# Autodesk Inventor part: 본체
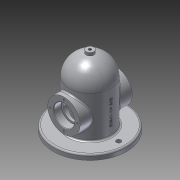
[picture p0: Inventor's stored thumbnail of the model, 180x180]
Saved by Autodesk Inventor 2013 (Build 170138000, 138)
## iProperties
Created: 2019-11
Part Number: 본체
Material: 알루미늄 6061
Document SubType Name: Modeling
Designer: Administrator
Density: 2.71 g/cm^3
Mass: 1110.07 g
Surface Area: 883.581 cm^2
Volume: 409.619 cm^3
Author: Administrator
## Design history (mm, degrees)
sketch "스케치4"
  geometry: C1 r 40 at (0, 0); 1 further point
  constraints: 1 centre point, 1 coincident
  dimensions: "d5" = 80 diameter of C1
extrude "돌출1" new body sketch "스케치4" distance "d7" = 90; taper "d8" = 0 deg
sketch "스케치5"
  geometry: L1 (-40, 0)-(-40, 90) reference; L2 (40, 90)-(-40, 90) reference; L3 (-40, 90)-(40, 90); L4 (40, 0)-(40, 90) reference; L5 (0, 0)-(0, 90); A1 r 40 centre (0, 90) between (40, 90) and (-40, 90)
  constraints: 6 end point, 3 point on circle, 2 point on line, 1 centre point, 1 coincident, 1 midpoint
revolve "회전1" sketch "스케치5" stored, may be unused: angle "d9" = 90 deg
sketch "스케치6"
  geometry: C1 r 40 at (0, 0) reference
feature "쉘1" dims "d10" = 10
sketch "스케치7"
  geometry: C1 r 40 at (0, 0); C2 r 70 at (0, 0); 1 further point
  constraints: 2 centre point, 2 coincident
  dimensions: "d13" = 80 diameter of C1; "d15" = 140 diameter of C2
extrude "돌출2" join sketch "스케치7" distance "d16" = 10; taper "d17" = 0 deg
node "작업 평면1"
sketch "스케치13"
  geometry: C1 r 7.5 at (0, 0); 1 further point
  constraints: 1 centre point, 1 coincident
  dimensions: "d38" = 15 diameter of C1
extrude "돌출5" join sketch "스케치13" stored distance "d40" = 15; taper "d41" = 0 deg
sketch "스케치14"
  geometry: C1 r 7.5 at (0, 0) reference
hole "구멍1" sketch "스케치14" at (0, 0) diameter "d42" = 5.188; stored, may be unused: countersink angle "d46" = 90 deg, drill point angle "d48" = 118 deg; dims "d43" = 6, "d44" = 4, "d45" = 2, "d47" = 8
node "작업 평면2"
sketch "스케치20"
  geometry: L1 (0, 0)-(0, 50); L2 (30, 0)-(-30, 0) reference; C1 r 31 at (0, 50)
  constraints: 2 end point, 1 centre point, 1 coincident, 1 perpendicular
  dimensions: "d61" = 50 distance of L1.start L1.end; "d62" = 62 diameter of C1
extrude "돌출6" join sketch "스케치20" stored distance "d63" = 15; taper "d64" = 0 deg
fillet "모깎기2" dims "d65" = 3
sketch "스케치21"
  geometry: C1 r 31 at (0, 0) reference; C2 r 20 at (0, 0); 1 further point
  constraints: 1 centre point, 1 coincident
  dimensions: "d66" = 40 diameter of C2
extrude "돌출7" cut sketch "스케치21" distance "d68" = 15; taper "d69" = 0 deg
sketch "스케치22"
  geometry: C1 r 20 at (0, 0) reference; C2 r 16.5 at (0, 0); 1 further point
  constraints: 1 centre point, 1 coincident
  dimensions: "d70" = 33 diameter of C2
extrude "돌출8" cut sketch "스케치22" stored distance "d72" = 15; taper "d73" = 0 deg
fillet "모깎기3" dims "d74" = 3
fillet "모깎기4" dims "d75" = 0.3
chamfer "모따기3" distance "d76" = 1; stored, may be unused: second distance "d77" = 2, angle "d78" = 45 deg
chamfer "모따기4" distance "d79" = 1; stored, may be unused: second distance "d80" = 2, angle "d81" = 45 deg
sketch "스케치23"
  geometry: L1 (0, 0)-(0, 26); C1 r 21 at (0, 0) reference; 1 further point
  constraints: 2 end point, 1 vertical
  dimensions: "d82" = 26 distance of L1.start L1.end
hole "구멍3" sketch "스케치23" at (0, 26) diameter "d83" = 3.242; stored, may be unused: countersink angle "d87" = 82 deg, drill point angle "d89" = 118 deg; dims "d84" = 8, "d85" = 3.023, "d86" = 2, "d88" = 10
fillet "모깎기5" dims "d93" = 3
sketch "스케치25"
  geometry: L1 (0, 0)-(55, 0); C1 r 43 at (0, 0) reference; C2 r 4.5 at (55, 0)
  constraints: 2 end point, 1 centre point, 1 coincident, 1 horizontal
  dimensions: "d94" = 55 distance of L1.start L1.end; "d95" = 9 diameter of C2
extrude "돌출9" cut sketch "스케치25" stored distance "d96" = 15; taper "d97" = 0 deg
node "작업 평면4"
sketch "스케치26"
  geometry: L1 (-70, 0)-(70, 0) reference; 2 further points
  constraints: 1 vertical alignment, 1 other
  dimensions: "d103" = 50 distance from line of L1 point (0, 50)
feature "엠보싱1" sketch "스케치26" dims "d7" = 90, "d104" = 0.5, "d105" = 0
node "솔리드1"
mirror "대칭4"
pattern_circular "원형 패턴2" dims angle "d91" = 360 deg
mirror "대칭5"
pattern_circular "원형 패턴3" dims angle "d99" = 360 deg
other parameters: "d37" = 135, "d102" = 62
